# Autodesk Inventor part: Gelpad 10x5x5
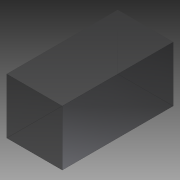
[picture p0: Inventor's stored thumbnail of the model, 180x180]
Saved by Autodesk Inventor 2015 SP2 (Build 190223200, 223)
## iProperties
Created: 2015-08
Part Number: Gelpad 10x5x5
Material: Gummi, Silikon
Document SubType Name: Modeling
Designer: ryll
Mass: 0.125 g
Surface Area: 1.6 cm^2
Volume: 0.1 cm^3
Density: 1.25 g/cm^3
Appearance: Gummi - schwarz - Version 1.1
Author: ryll
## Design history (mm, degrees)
sketch "Skizze1"
  geometry: L1 (-2.5, 5)-(2.5, 5); L2 (2.5, 5)-(2.5, -5); L3 (2.5, -5)-(-2.5, -5); L4 (-2.5, -5)-(-2.5, 5); L5 (-3.5, 0)-(3.5, 0) reference; L6 (0, 7)-(0, -7) reference; 1 further point
  constraints: 8 end point, 2 parallel, 1 horizontal, 1 perpendicular, 2 other
  dimensions: "d0" = 5 distance of L1.start L1.end; "d1" = 10 distance of L1.end L2.end
extrude "Extrusion1" new body sketch "Skizze1" distance "d2" = 5; taper "d3" = 0 deg
node "Volumenkörper1"
